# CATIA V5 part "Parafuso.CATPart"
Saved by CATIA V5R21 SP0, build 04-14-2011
Part number: Parafuso
Definition: Parafuso
Nomenclature: Parafuso
Source: Unknown
Bounding box of the stored display mesh (mm): x -1.25 to 1.25, y 0 to 10, z -1.25 to 1.25
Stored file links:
  C:\Users\beatr\OneDrive\Documents\UNB\2026_1\Pi1\Componentes eletronicos\Parafuso.CATPart
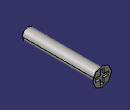
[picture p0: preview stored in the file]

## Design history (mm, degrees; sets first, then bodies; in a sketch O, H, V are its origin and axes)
Body1 "Sólido1" (main body)
  Solid1: solid without history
